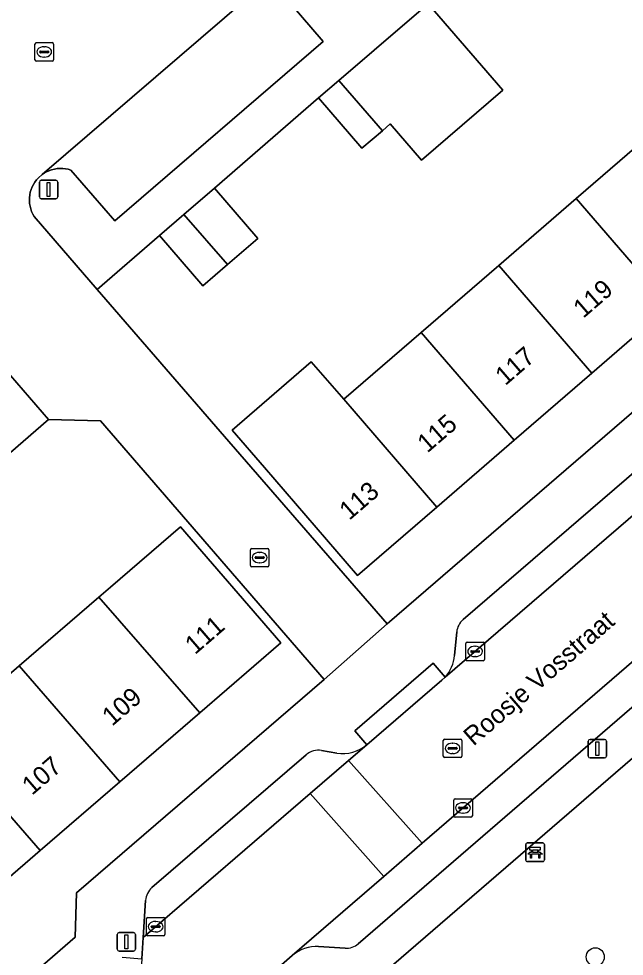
# Model space of a CAD drawing. Extents: x 160304 to 160955, y 383684 to 384161.
# Drawn here: x 160574.4 to 160607.1, y 384048.1 to 384098.8 of the extents above; entities that cross this region are included whole.
import ezdxf

# ---------------------------------------------------------------- set-up
doc = ezdxf.new("R2010")
doc.units = 0
for name, color, linetype in [('IMGEO_Bank', 7, 'Continuous'), ('IMGEO_Boom', 7, 'Continuous'), ('IMGEO_Erf', 7, 'Continuous'), ('IMGEO_Groenvoorziening', 7, 'Continuous'), ('IMGEO_Kolk', 7, 'Continuous'), ('IMGEO_Lichtmast', 7, 'Continuous'), ('IMGEO_Muur', 7, 'Continuous'), ('IMGEO_Openbare_ruimte_label', 7, 'Continuous'), ('IMGEO_Pand', 7, 'Continuous'), ('IMGEO_Pand_nummerreeks', 7, 'Continuous'), ('IMGEO_Parkeervlak_open', 7, 'Continuous'), ('IMGEO_Rijbaan_lokaal_open', 7, 'Continuous'), ('IMGEO_Rioolput', 7, 'Continuous'), ('IMGEO_Voetpad_open', 7, 'Continuous')]:
    doc.layers.add(name, color=color, linetype=linetype)

msp = doc.modelspace()

# ---------------------------------------------------------------- linework, layer by layer
at = {"layer": 'IMGEO_Bank'}
for p, q in [((160601.786, 384053.301), (160601.786, 384054.142)), ((160601.786, 384054.142), (160601.786, 384053.301)), ((160601.861, 384054.226), (160602.702, 384054.226)), ((160602.702, 384054.226), (160601.861, 384054.226)), ((160602.095, 384053.732), (160602.095, 384053.838)), ((160602.139, 384053.838), (160602.139, 384053.732)), ((160602.427, 384053.844), (160602.145, 384053.844)), ((160602.433, 384053.732), (160602.433, 384053.838)), ((160602.477, 384053.838), (160602.477, 384053.732)), ((160602.786, 384054.151), (160602.786, 384053.31)), ((160602.786, 384053.31), (160602.786, 384054.151)), ((160602.483, 384053.624), (160602.09, 384053.624)), ((160602.145, 384053.726), (160602.427, 384053.726)), ((160602.711, 384053.226), (160601.87, 384053.226)), ((160601.87, 384053.226), (160602.711, 384053.226))]:
    msp.add_line(p, q, dxfattribs=at)
for points in [[(160602.089, 384053.844), (160602.003, 384053.844), (160602.003, 384054.005), (160602.566, 384054.005), (160602.566, 384053.844), (160602.483, 384053.844)], [(160602.033, 384053.624), (160601.891, 384053.624), (160602.003, 384053.726), (160602.089, 384053.726)], [(160602.083, 384053.617), (160602.083, 384053.41), (160602.04, 384053.41), (160602.04, 384053.617)], [(160602.483, 384053.726), (160602.566, 384053.726), (160602.678, 384053.624), (160602.539, 384053.624)], [(160602.533, 384053.617), (160602.533, 384053.41), (160602.489, 384053.41), (160602.489, 384053.617)]]:
    msp.add_lwpolyline(points, dxfattribs=at)
for centre, radius, start, end in [((160601.864, 384054.148), 0.0779, 92.4484, 184.2845), ((160601.864, 384054.148), 0.0779, 92.4484, 184.2845), ((160602.088, 384053.837), 0.00671, 2.8957, 87.1043), ((160602.145, 384053.837), 0.00671, 92.8957, 177.1043), ((160602.427, 384053.837), 0.00671, 2.8957, 87.1043), ((160602.484, 384053.837), 0.00671, 92.8957, 177.1043), ((160602.708, 384054.148), 0.0779, 2.4484, 94.2845), ((160602.708, 384054.148), 0.0779, 2.4484, 94.2845), ((160601.864, 384053.304), 0.0779, 182.4484, 274.2845), ((160601.864, 384053.304), 0.0779, 182.4484, 274.2845), ((160602.033, 384053.617), 0.00671, 2.8957, 87.1043), ((160602.09, 384053.617), 0.00671, 92.8957, 177.1043), ((160602.088, 384053.733), 0.00671, 272.8957, 357.1043), ((160602.145, 384053.733), 0.00671, 182.8957, 267.1043), ((160602.427, 384053.733), 0.00671, 272.8957, 357.1043), ((160602.484, 384053.733), 0.00671, 182.8957, 267.1043), ((160602.482, 384053.617), 0.00671, 2.8957, 87.1043), ((160602.539, 384053.617), 0.00671, 92.8957, 177.1043), ((160602.708, 384053.304), 0.0779, 272.4484, 4.2845), ((160602.708, 384053.304), 0.0779, 272.4484, 4.2845)]:
    msp.add_arc(centre, radius, start, end, dxfattribs=at)
at = {"layer": 'IMGEO_Boom'}
msp.add_circle((160605.538, 384048.071), 0.489, dxfattribs=at)
at = {"layer": 'IMGEO_Erf'}
for points in [[(160628.076, 384099.249), (160622.188, 384094.164), (160617.912, 384090.471), (160613.725, 384086.854), (160609.537, 384083.236), (160605.35, 384079.62), (160601.162, 384076.003), (160596.974, 384072.386), (160592.694, 384068.69), (160587.665, 384074.513), (160585.913, 384076.542), (160590.193, 384080.238), (160591.945, 384078.209), (160596.133, 384081.826), (160600.321, 384085.443), (160604.508, 384089.059), (160608.696, 384092.676), (160612.884, 384096.293), (160617.168, 384099.994)], [(160596.516, 384099.592), (160600.543, 384094.908), (160596.147, 384091.129), (160594.461, 384093.091), (160594.033, 384092.723), (160592.93, 384091.775), (160590.59, 384094.497), (160584.964, 384089.625), (160587.307, 384086.905), (160585.661, 384085.486), (160584.326, 384084.335), (160581.982, 384087.055), (160578.615, 384084.142), (160585.508, 384076.191), (160594.287, 384066.063), (160630.096, 384096.946)], [(160562.223, 384035.951), (160577.428, 384049.127), (160577.514, 384051.539), (160590.891, 384063.065), (160578.802, 384077.039), (160575.999, 384077.117), (160571.605, 384073.322)], [(160570.102, 384060.072), (160574.41, 384063.793), (160578.719, 384067.513), (160579.338, 384068.048), (160583.122, 384071.316), (160588.539, 384065.044), (160584.165, 384061.267), (160579.845, 384057.535), (160575.545, 384053.821), (160571.219, 384050.086)]]:
    msp.add_lwpolyline(points, dxfattribs=at)
at = {"layer": 'IMGEO_Groenvoorziening'}
msp.add_lwpolyline([(160607.555, 384058.819), (160588.993, 384042.795)], dxfattribs=at)
at = {"layer": 'IMGEO_Kolk'}
for p, q in [((160575.26, 384096.559), (160575.26, 384097.411)), ((160575.335, 384097.485), (160576.187, 384097.485)), ((160576.261, 384097.411), (160576.261, 384096.559)), ((160575.519, 384096.979), (160575.519, 384096.991)), ((160575.957, 384096.942), (160575.559, 384096.942)), ((160575.562, 384097.028), (160575.96, 384097.028)), ((160575.748, 384097.265), (160575.773, 384097.265)), ((160576.003, 384096.991), (160576.003, 384096.979)), ((160576.187, 384096.485), (160575.335, 384096.485)), ((160575.771, 384096.705), (160575.746, 384096.705)), ((160586.905, 384069.225), (160586.905, 384070.077)), ((160586.98, 384070.151), (160587.832, 384070.151)), ((160587.906, 384070.077), (160587.906, 384069.225)), ((160587.164, 384069.645), (160587.164, 384069.657)), ((160587.602, 384069.608), (160587.204, 384069.608)), ((160587.207, 384069.694), (160587.605, 384069.694)), ((160587.393, 384069.931), (160587.418, 384069.931)), ((160587.648, 384069.657), (160587.648, 384069.645)), ((160587.832, 384069.151), (160586.98, 384069.151)), ((160587.416, 384069.371), (160587.391, 384069.371)), ((160598.546, 384064.152), (160598.546, 384065.004)), ((160598.621, 384065.078), (160599.473, 384065.078)), ((160599.547, 384065.004), (160599.547, 384064.152)), ((160598.805, 384064.572), (160598.805, 384064.584)), ((160599.243, 384064.535), (160598.845, 384064.535)), ((160598.848, 384064.621), (160599.246, 384064.621)), ((160599.034, 384064.858), (160599.059, 384064.858)), ((160599.289, 384064.584), (160599.289, 384064.572)), ((160599.473, 384064.078), (160598.621, 384064.078)), ((160599.057, 384064.298), (160599.032, 384064.298)), ((160597.894, 384055.695), (160597.894, 384056.547)), ((160597.969, 384056.621), (160598.821, 384056.621)), ((160598.382, 384056.401), (160598.407, 384056.401)), ((160598.895, 384056.547), (160598.895, 384055.695)), ((160598.153, 384056.115), (160598.153, 384056.127)), ((160598.591, 384056.078), (160598.193, 384056.078)), ((160598.196, 384056.164), (160598.594, 384056.164)), ((160598.405, 384055.841), (160598.38, 384055.841)), ((160598.637, 384056.127), (160598.637, 384056.115)), ((160598.821, 384055.621), (160597.969, 384055.621)), ((160581.282, 384049.277), (160581.282, 384050.129)), ((160581.357, 384050.203), (160582.209, 384050.203)), ((160581.77, 384049.983), (160581.795, 384049.983)), ((160582.283, 384050.129), (160582.283, 384049.277)), ((160581.541, 384049.697), (160581.541, 384049.709)), ((160581.979, 384049.66), (160581.581, 384049.66)), ((160581.584, 384049.746), (160581.982, 384049.746)), ((160581.793, 384049.423), (160581.768, 384049.423)), ((160582.025, 384049.709), (160582.025, 384049.697)), ((160582.209, 384049.203), (160581.357, 384049.203))]:
    msp.add_line(p, q, dxfattribs=at)
for points in [[(160575.26, 384096.559), (160575.26, 384097.411)], [(160575.335, 384097.485), (160576.187, 384097.485)], [(160576.261, 384097.411), (160576.261, 384096.559)], [(160576.187, 384096.485), (160575.335, 384096.485)], [(160586.905, 384069.225), (160586.905, 384070.077)], [(160586.98, 384070.151), (160587.832, 384070.151)], [(160587.906, 384070.077), (160587.906, 384069.225)], [(160587.832, 384069.151), (160586.98, 384069.151)], [(160598.546, 384064.152), (160598.546, 384065.004)], [(160598.621, 384065.078), (160599.473, 384065.078)], [(160599.547, 384065.004), (160599.547, 384064.152)], [(160599.473, 384064.078), (160598.621, 384064.078)], [(160597.894, 384055.695), (160597.894, 384056.547)], [(160597.969, 384056.621), (160598.821, 384056.621)], [(160598.895, 384056.547), (160598.895, 384055.695)], [(160598.821, 384055.621), (160597.969, 384055.621)], [(160581.282, 384049.277), (160581.282, 384050.129)], [(160581.357, 384050.203), (160582.209, 384050.203)], [(160582.283, 384050.129), (160582.283, 384049.277)], [(160582.209, 384049.203), (160581.357, 384049.203)]]:
    msp.add_lwpolyline(points, dxfattribs=at)
for centre, radius, start, end in [((160575.337, 384097.409), 0.0765, 91.552, 178.448), ((160575.337, 384097.409), 0.0765, 91.552, 178.448), ((160576.185, 384097.409), 0.0765, 1.552, 88.448), ((160576.185, 384097.409), 0.0765, 1.552, 88.448), ((160575.559, 384096.988), 0.0403, 85.8775, 175.7526), ((160575.556, 384096.978), 0.0366, 178.938, 274.7102), ((160575.96, 384096.985), 0.043, 264.8664, 352.4533), ((160575.964, 384096.99), 0.0386, 1.7309, 96.639), ((160575.337, 384096.561), 0.0765, 181.552, 268.448), ((160575.337, 384096.561), 0.0765, 181.552, 268.448), ((160576.185, 384096.561), 0.0765, 271.552, 358.448), ((160576.185, 384096.561), 0.0765, 271.552, 358.448), ((160586.982, 384070.075), 0.0765, 91.552, 178.448), ((160586.982, 384070.075), 0.0765, 91.552, 178.448), ((160587.83, 384070.075), 0.0765, 1.552, 88.448), ((160587.83, 384070.075), 0.0765, 1.552, 88.448), ((160587.204, 384069.654), 0.0403, 85.8775, 175.7526), ((160587.201, 384069.644), 0.0366, 178.938, 274.7102), ((160587.605, 384069.651), 0.043, 264.8664, 352.4533), ((160587.609, 384069.656), 0.0386, 1.7309, 96.639), ((160586.982, 384069.227), 0.0765, 181.552, 268.448), ((160586.982, 384069.227), 0.0765, 181.552, 268.448), ((160587.83, 384069.227), 0.0765, 271.552, 358.448), ((160587.83, 384069.227), 0.0765, 271.552, 358.448), ((160598.623, 384065.002), 0.0765, 91.552, 178.448), ((160598.623, 384065.002), 0.0765, 91.552, 178.448), ((160599.471, 384065.002), 0.0765, 1.552, 88.448), ((160599.471, 384065.002), 0.0765, 1.552, 88.448), ((160598.845, 384064.581), 0.0403, 85.8775, 175.7526), ((160598.842, 384064.571), 0.0366, 178.938, 274.7102), ((160599.246, 384064.578), 0.043, 264.8664, 352.4533), ((160599.25, 384064.583), 0.0386, 1.7309, 96.639), ((160598.623, 384064.154), 0.0765, 181.552, 268.448), ((160598.623, 384064.154), 0.0765, 181.552, 268.448), ((160599.471, 384064.154), 0.0765, 271.552, 358.448), ((160599.471, 384064.154), 0.0765, 271.552, 358.448), ((160597.971, 384056.545), 0.0765, 91.552, 178.448), ((160597.971, 384056.545), 0.0765, 91.552, 178.448), ((160598.819, 384056.545), 0.0765, 1.552, 88.448), ((160598.819, 384056.545), 0.0765, 1.552, 88.448), ((160598.193, 384056.124), 0.0403, 85.8775, 175.7526), ((160598.19, 384056.114), 0.0366, 178.938, 274.7102), ((160598.594, 384056.121), 0.043, 264.8664, 352.4533), ((160598.598, 384056.126), 0.0386, 1.7309, 96.639), ((160597.971, 384055.697), 0.0765, 181.552, 268.448), ((160597.971, 384055.697), 0.0765, 181.552, 268.448), ((160598.819, 384055.697), 0.0765, 271.552, 358.448), ((160598.819, 384055.697), 0.0765, 271.552, 358.448), ((160581.359, 384050.127), 0.0765, 91.552, 178.448), ((160581.359, 384050.127), 0.0765, 91.552, 178.448), ((160582.207, 384050.127), 0.0765, 1.552, 88.448), ((160582.207, 384050.127), 0.0765, 1.552, 88.448), ((160581.359, 384049.279), 0.0765, 181.552, 268.448), ((160581.359, 384049.279), 0.0765, 181.552, 268.448), ((160581.581, 384049.706), 0.0403, 85.8775, 175.7526), ((160581.578, 384049.696), 0.0366, 178.938, 274.7102), ((160581.982, 384049.703), 0.043, 264.8664, 352.4533), ((160581.986, 384049.708), 0.0386, 1.7309, 96.639), ((160582.207, 384049.279), 0.0765, 271.552, 358.448), ((160582.207, 384049.279), 0.0765, 271.552, 358.448)]:
    msp.add_arc(centre, radius, start, end, dxfattribs=at)
for centre, major_axis, ratio, start_param, end_param in [((160575.747, 384096.985), (-0.387, 0.002), 0.722429, 4.712389, 7.853982), ((160575.772, 384096.985), (-0.39, 0.002), 0.717154, 1.570796, 4.712389), ((160587.392, 384069.651), (-0.387, 0.002), 0.722429, 4.712389, 7.853982), ((160587.417, 384069.651), (-0.39, 0.002), 0.717154, 1.570796, 4.712389), ((160599.033, 384064.578), (-0.387, 0.002), 0.722429, 4.712389, 7.853982), ((160599.058, 384064.578), (-0.39, 0.002), 0.717154, 1.570796, 4.712389), ((160598.381, 384056.121), (-0.387, 0.002), 0.722429, 4.712389, 7.853982), ((160598.406, 384056.121), (-0.39, 0.002), 0.717154, 1.570796, 4.712389), ((160581.769, 384049.703), (-0.387, 0.002), 0.722429, 4.712389, 7.853982), ((160581.794, 384049.703), (-0.39, 0.002), 0.717154, 1.570796, 4.712389)]:
    msp.add_ellipse(centre, major_axis=major_axis, ratio=ratio, start_param=start_param, end_param=end_param, dxfattribs=at)
at = {"layer": 'IMGEO_Lichtmast'}
for p, q in [((160575.499, 384089.15), (160575.499, 384089.95)), ((160575.499, 384089.95), (160575.499, 384089.15)), ((160575.599, 384090.05), (160576.389, 384090.05)), ((160576.389, 384090.05), (160575.599, 384090.05)), ((160576.489, 384089.95), (160576.489, 384089.15)), ((160576.489, 384089.15), (160576.489, 384089.95)), ((160576.389, 384089.05), (160575.599, 384089.05)), ((160575.599, 384089.05), (160576.389, 384089.05)), ((160605.154, 384058.923), (160605.154, 384059.723)), ((160605.154, 384059.723), (160605.154, 384058.923)), ((160605.254, 384059.823), (160606.044, 384059.823)), ((160606.044, 384059.823), (160605.254, 384059.823)), ((160606.144, 384059.723), (160606.144, 384058.923)), ((160606.144, 384058.923), (160606.144, 384059.723)), ((160606.044, 384058.823), (160605.254, 384058.823)), ((160605.254, 384058.823), (160606.044, 384058.823)), ((160579.703, 384048.482), (160579.703, 384049.282)), ((160579.703, 384049.282), (160579.703, 384048.482)), ((160579.803, 384049.382), (160580.593, 384049.382)), ((160580.593, 384049.382), (160579.803, 384049.382)), ((160580.693, 384049.282), (160580.693, 384048.482)), ((160580.693, 384048.482), (160580.693, 384049.282)), ((160580.593, 384048.382), (160579.803, 384048.382)), ((160579.803, 384048.382), (160580.593, 384048.382))]:
    msp.add_line(p, q, dxfattribs=at)
for points in [[(160575.919, 384089.925), (160576.069, 384089.925), (160576.069, 384089.175), (160575.919, 384089.175), (160575.919, 384089.925)], [(160605.574, 384059.698), (160605.724, 384059.698), (160605.724, 384058.948), (160605.574, 384058.948), (160605.574, 384059.698)], [(160580.123, 384049.257), (160580.273, 384049.257), (160580.273, 384048.507), (160580.123, 384048.507), (160580.123, 384049.257)]]:
    msp.add_lwpolyline(points, dxfattribs=at)
for centre, start, end in [((160575.599, 384089.95), 90, 180), ((160575.599, 384089.95), 90, 180), ((160576.389, 384089.95), 0, 90), ((160576.389, 384089.95), 360, 90), ((160575.599, 384089.15), 180, 270), ((160575.599, 384089.15), 180, 270), ((160576.389, 384089.15), 270, 0), ((160576.389, 384089.15), 270, 0), ((160605.254, 384059.723), 90, 180), ((160605.254, 384059.723), 90, 180), ((160606.044, 384059.723), 0, 90), ((160606.044, 384059.723), 360, 90), ((160605.254, 384058.923), 180, 270), ((160605.254, 384058.923), 180, 270), ((160606.044, 384058.923), 270, 0), ((160606.044, 384058.923), 270, 0), ((160579.803, 384049.282), 90, 180), ((160579.803, 384049.282), 90, 180), ((160580.593, 384049.282), 0, 90), ((160580.593, 384049.282), 360, 90), ((160579.803, 384048.482), 180, 270), ((160579.803, 384048.482), 180, 270), ((160580.593, 384048.482), 270, 0), ((160580.593, 384048.482), 270, 0)]:
    msp.add_arc(centre, 0.1, start, end, dxfattribs=at)
at = {"layer": 'IMGEO_Muur'}
for points in [[(160578.615, 384084.142), (160581.982, 384087.055)], [(160585.508, 384076.191), (160578.615, 384084.142)]]:
    msp.add_lwpolyline(points, dxfattribs=at)
at = {"layer": 'IMGEO_Pand'}
for points in [[(160596.516, 384099.592), (160593.583, 384097.07), (160591.687, 384095.44), (160594.033, 384092.723), (160594.461, 384093.091), (160596.147, 384091.129), (160600.543, 384094.908)], [(160591.687, 384095.44), (160590.59, 384094.497), (160592.93, 384091.775), (160594.033, 384092.723)], [(160609.537, 384083.236), (160613.725, 384086.854), (160608.696, 384092.676), (160604.508, 384089.059)], [(160585.661, 384085.486), (160587.307, 384086.905), (160584.964, 384089.625), (160583.314, 384088.203)], [(160600.321, 384085.443), (160605.35, 384079.62), (160609.537, 384083.236), (160604.508, 384089.059)], [(160585.661, 384085.486), (160583.314, 384088.203), (160581.982, 384087.055), (160584.326, 384084.335)], [(160600.321, 384085.443), (160596.133, 384081.826), (160601.162, 384076.003), (160605.35, 384079.62)], [(160596.974, 384072.386), (160601.162, 384076.003), (160596.133, 384081.826), (160591.945, 384078.209)], [(160596.974, 384072.386), (160591.945, 384078.209), (160590.193, 384080.238), (160585.913, 384076.542), (160587.665, 384074.513), (160592.694, 384068.69)], [(160569.209, 384076.095), (160571.605, 384073.322), (160575.999, 384077.117), (160573.604, 384079.891)], [(160578.719, 384067.513), (160584.165, 384061.267), (160588.539, 384065.044), (160583.122, 384071.316), (160579.338, 384068.048)], [(160574.41, 384063.793), (160579.845, 384057.535), (160584.165, 384061.267), (160578.719, 384067.513)], [(160575.545, 384053.821), (160579.845, 384057.535), (160574.41, 384063.793), (160570.102, 384060.072)], [(160575.545, 384053.821), (160570.102, 384060.072), (160565.799, 384056.356), (160571.219, 384050.086)]]:
    msp.add_lwpolyline(points, close=True, dxfattribs=at)
at = {"layer": 'IMGEO_Parkeervlak_open'}
msp.add_lwpolyline([(160587.929, 384100.937), (160575.655, 384090.36), (160575.75, 384090.425), (160575.882, 384090.501), (160576.02, 384090.564), (160576.163, 384090.615), (160576.31, 384090.652), (160576.46, 384090.677), (160576.611, 384090.688), (160576.763, 384090.685), (160576.914, 384090.669), (160577.062, 384090.64), (160577.208, 384090.597), (160579.575, 384087.85), (160590.827, 384097.546)], close=True, dxfattribs=at)
for points in [[(160632.328, 384095.537), (160631.761, 384095.048), (160598.394, 384066.298)], [(160597.427, 384063.191), (160628.391, 384089.864)], [(160611.687, 384067.609), (160596.18, 384054.208), (160594.111, 384052.42), (160589.163, 384048.144)], [(160598.051, 384065.632), (160597.934, 384064.359)], [(160592.733, 384048.779), (160610.683, 384064.29)], [(160581.24, 384051.121), (160581.111, 384049.123), (160590.131, 384056.895), (160592.207, 384058.683), (160593.19, 384059.531)], [(160589.923, 384058.999), (160581.585, 384051.814)], [(160591.577, 384059.089), (160590.739, 384059.228)], [(160590.591, 384048.625), (160592.018, 384048.537)]]:
    msp.add_lwpolyline(points, dxfattribs=at)
for centre, radius, start, end in [((160599.051, 384065.538), 1.004, 130.8562, 174.6455), ((160595.923, 384064.538), 2.019, 318.1536, 354.9174), ((160591.904, 384061.059), 1.997, 260.5677, 310.0807), ((160590.577, 384058.238), 1.003, 80.6908, 130.6614), ((160582.242, 384051.055), 1.004, 130.8634, 176.2051), ((160592.078, 384049.537), 1.001, 266.5598, 310.8381), ((160590.513, 384046.497), 2.13, 87.8977, 129.3329)]:
    msp.add_arc(centre, radius, start, end, dxfattribs=at)
at = {"layer": 'IMGEO_Rijbaan_lokaal_open'}
for points in [[(160573.604, 384079.891), (160575.999, 384077.117), (160578.802, 384077.039), (160590.891, 384063.065), (160594.287, 384066.063), (160585.508, 384076.191), (160578.615, 384084.142), (160575.218, 384088.092), (160575.146, 384088.22), (160575.083, 384088.358), (160575.033, 384088.501), (160574.995, 384088.648), (160574.971, 384088.798), (160574.961, 384088.949), (160574.964, 384089.101), (160574.981, 384089.252), (160575.011, 384089.401), (160575.054, 384089.546), (160575.11, 384089.687), (160575.178, 384089.823), (160575.259, 384089.951), (160575.35, 384090.073), (160575.452, 384090.185), (160575.655, 384090.36), (160587.929, 384100.937)], [(160594.111, 384052.42), (160590.131, 384056.895), (160581.111, 384049.123), (160581.037, 384047.97), (160580.353, 384037.334)], [(160588.016, 384047.153), (160589.163, 384048.144), (160594.111, 384052.42)]]:
    msp.add_lwpolyline(points, dxfattribs=at)
for points in [[(160632.284, 384085.335), (160628.391, 384089.864), (160597.427, 384063.191), (160597.248, 384063.027), (160593.19, 384059.531), (160592.207, 384058.683), (160596.18, 384054.208), (160611.687, 384067.609), (160613.509, 384069.183), (160625.278, 384079.272), (160628.038, 384081.66)], [(160590.131, 384056.895), (160594.111, 384052.42), (160596.18, 384054.208), (160592.207, 384058.683)]]:
    msp.add_lwpolyline(points, close=True, dxfattribs=at)
at = {"layer": 'IMGEO_Rioolput'}
for p, q in [((160597.325, 384058.914), (160597.325, 384059.766)), ((160597.4, 384059.84), (160598.252, 384059.84)), ((160597.627, 384059.383), (160598.025, 384059.383)), ((160597.813, 384059.62), (160597.838, 384059.62)), ((160598.326, 384059.766), (160598.326, 384058.914)), ((160597.584, 384059.334), (160597.584, 384059.346)), ((160598.022, 384059.297), (160597.624, 384059.297)), ((160597.836, 384059.06), (160597.811, 384059.06)), ((160598.068, 384059.346), (160598.068, 384059.334)), ((160598.252, 384058.84), (160597.4, 384058.84))]:
    msp.add_line(p, q, dxfattribs=at)
for points in [[(160597.325, 384058.914), (160597.325, 384059.766)], [(160597.4, 384059.84), (160598.252, 384059.84)], [(160598.326, 384059.766), (160598.326, 384058.914)], [(160598.252, 384058.84), (160597.4, 384058.84)]]:
    msp.add_lwpolyline(points, dxfattribs=at)
for centre, radius, start, end in [((160597.402, 384059.764), 0.0765, 91.552, 178.448), ((160597.402, 384059.764), 0.0765, 91.552, 178.448), ((160597.624, 384059.343), 0.0403, 85.8775, 175.7526), ((160598.029, 384059.345), 0.0386, 1.7309, 96.639), ((160598.25, 384059.764), 0.0765, 1.552, 88.448), ((160598.25, 384059.764), 0.0765, 1.552, 88.448), ((160597.402, 384058.916), 0.0765, 181.552, 268.448), ((160597.402, 384058.916), 0.0765, 181.552, 268.448), ((160597.621, 384059.333), 0.0366, 178.938, 274.7102), ((160598.025, 384059.34), 0.043, 264.8664, 352.4533), ((160598.25, 384058.916), 0.0765, 271.552, 358.448), ((160598.25, 384058.916), 0.0765, 271.552, 358.448)]:
    msp.add_arc(centre, radius, start, end, dxfattribs=at)
for centre, major_axis, ratio, start_param, end_param in [((160597.812, 384059.34), (-0.387, 0.002), 0.722429, 4.712389, 7.853982), ((160597.837, 384059.34), (-0.39, 0.002), 0.717154, 1.570796, 4.712389)]:
    msp.add_ellipse(centre, major_axis=major_axis, ratio=ratio, start_param=start_param, end_param=end_param, dxfattribs=at)
at = {"layer": 'IMGEO_Voetpad_open'}
for points in [[(160587.929, 384100.937), (160590.827, 384097.546), (160579.575, 384087.85), (160577.208, 384090.597), (160577.062, 384090.64), (160576.914, 384090.669), (160576.763, 384090.685), (160576.611, 384090.688), (160576.46, 384090.677), (160576.31, 384090.652), (160576.163, 384090.615), (160576.02, 384090.564), (160575.882, 384090.501), (160575.75, 384090.425), (160575.655, 384090.36), (160575.452, 384090.185), (160575.35, 384090.073), (160575.259, 384089.951), (160575.178, 384089.823), (160575.11, 384089.687), (160575.054, 384089.546), (160575.011, 384089.401), (160574.981, 384089.252), (160574.964, 384089.101), (160574.961, 384088.949), (160574.971, 384088.798), (160574.995, 384088.648), (160575.033, 384088.501), (160575.083, 384088.358), (160575.146, 384088.22), (160575.218, 384088.092), (160578.615, 384084.142), (160581.982, 384087.055), (160583.314, 384088.203), (160584.964, 384089.625), (160590.59, 384094.497), (160591.687, 384095.44), (160593.583, 384097.07), (160596.516, 384099.592)], [(160598.394, 384066.298), (160631.761, 384095.048), (160630.096, 384096.946), (160594.287, 384066.063), (160590.891, 384063.065), (160577.514, 384051.539), (160577.428, 384049.127), (160562.223, 384035.951), (160561.983, 384032.44), (160563.316, 384032.344), (160563.431, 384033.622)], [(160597.934, 384064.359), (160598.051, 384065.632)], [(160593.19, 384059.531), (160592.537, 384060.288), (160596.775, 384063.949), (160597.427, 384063.191)], [(160610.683, 384064.29), (160592.733, 384048.779)], [(160581.585, 384051.814), (160589.923, 384058.999)], [(160590.739, 384059.228), (160591.577, 384059.089)], [(160588.993, 384042.795), (160607.555, 384058.819)], [(160579.979, 384048.063), (160581.037, 384047.97), (160581.111, 384049.123), (160581.24, 384051.121)], [(160592.018, 384048.537), (160590.591, 384048.625)], [(160589.163, 384048.144), (160588.016, 384047.153)]]:
    msp.add_lwpolyline(points, dxfattribs=at)
msp.add_lwpolyline([(160593.19, 384059.531), (160597.248, 384063.027), (160597.427, 384063.191), (160596.775, 384063.949), (160592.537, 384060.288)], close=True, dxfattribs=at)
for centre, radius, start, end in [((160599.051, 384065.538), 1.004, 130.8562, 174.6455), ((160595.923, 384064.538), 2.019, 318.1536, 354.9174), ((160591.904, 384061.059), 1.997, 260.5677, 310.0807), ((160590.577, 384058.238), 1.003, 80.6908, 130.6614), ((160582.242, 384051.055), 1.004, 130.8634, 176.2051), ((160592.078, 384049.537), 1.001, 266.5598, 310.8381), ((160590.513, 384046.497), 2.13, 87.8977, 129.3329)]:
    msp.add_arc(centre, radius, start, end, dxfattribs=at)

# ---------------------------------------------------------------- texts
at = {"layer": 'IMGEO_Openbare_ruimte_label'}
msp.add_text('Roosje Vosstraat', height=1, rotation=40.8249, dxfattribs=at).set_placement((160598.957, 384059.431))
at = {"layer": 'IMGEO_Pand_nummerreeks'}
for s, rotation, p in [('119', 40.8172, (160604.889, 384082.553)), ('117', 40.8172, (160600.676, 384078.914)), ('115', 40.8172, (160596.463, 384075.274)), ('113', 40.8172, (160592.249, 384071.635)), ('111', 40.8144, (160583.91, 384064.376)), ('109', 40.8144, (160579.429, 384060.506)), ('107', 40.8144, (160575.103, 384056.77))]:
    msp.add_text(s, height=1, rotation=rotation, dxfattribs=at).set_placement(p)

doc.saveas('drawing.dxf')
